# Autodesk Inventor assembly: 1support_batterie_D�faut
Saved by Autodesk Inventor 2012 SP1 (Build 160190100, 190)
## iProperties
Created: 2011-01
Part Number: 1support_batterie_D�faut
Document SubType Name: Assembly
Designer: eric
Mass: 42.3789 g
Surface Area: 218.745 cm^2
Volume: 42.3789 cm^3
Density: 1 g/cm^3
Author: eric
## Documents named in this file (5)
- D:\Cours\Inventor salle SI\chariot_de_golf_2008\chariot_de_golf_trolem\1support_batterie_Defaut.iam
- D:\Cours\Inventor salle SI\chariot_de_golf_2008\chariot_de_golf_trolem\bead13_Defaut.ipt
- D:\Cours\Inventor salle SI\chariot_de_golf_2008\chariot_de_golf_trolem\1rond_coude2_Defaut.ipt
- D:\Cours\Inventor salle SI\chariot_de_golf_2008\chariot_de_golf_trolem\bead12_Defaut.ipt
- D:\Cours\Inventor salle SI\chariot_de_golf_2008\chariot_de_golf_trolem\1rond_coude1_Defaut.ipt
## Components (4 placed, 4 different names)
1. bead13_Defaut:1
2. 1rond_coude2_Defaut:1
3. bead12_Defaut:1
4. 1rond_coude1_Defaut:1
